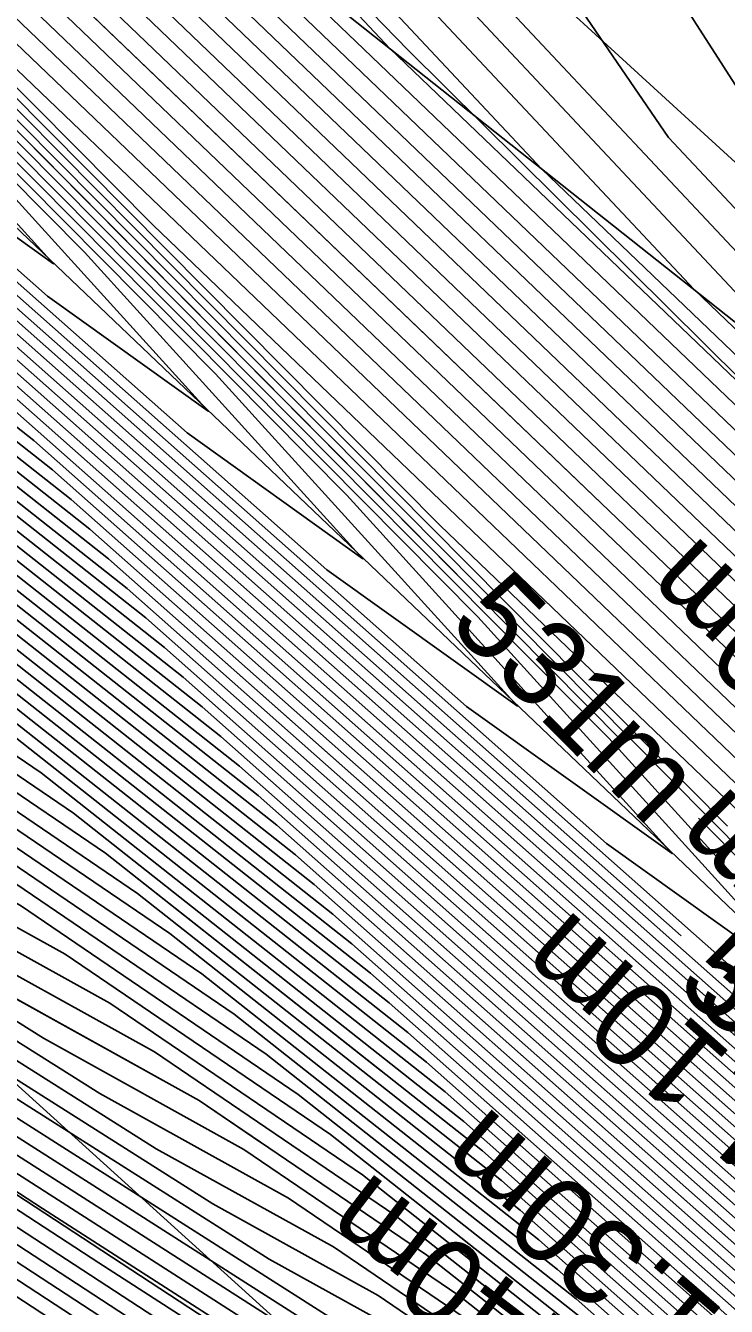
# Model space of a CAD drawing. Extents: x -866683 to -866410, y -1041951 to -1040252.
# Drawn here: x -866433.64 to -866431.189, y -1041924.913 to -1041920.429 of the extents above; entities that cross this region are included whole.
import ezdxf

# ---------------------------------------------------------------- set-up
doc = ezdxf.new("R2010")
doc.units = 0
for name, color, linetype in [('BREAKLINE', 7, 'Continuous'), ('V-HL', 7, 'Continuous'), ('V-POPIS', 7, 'Continuous'), ('V-VEDL', 7, 'Continuous'), ('V_po_cm', 7, 'Continuous')]:
    doc.layers.add(name, color=color, linetype=linetype)

msp = doc.modelspace()

# ---------------------------------------------------------------- linework, layer by layer
at = {"layer": 'BREAKLINE'}
for points in [[(-866451.679, -1041950.508), (-866455.618, -1041922.473), (-866456.719, -1041912.396), (-866455.207, -1041909.853), (-866453.752, -1041908.342), (-866450, -1041907.538), (-866447.7, -1041908.076), (-866445.165, -1041909.459), (-866437.422, -1041915.176), (-866426.565, -1041925.108), (-866438.22, -1041915.868), (-866445.312, -1041910.554), (-866447.7, -1041908.076)], [(-866445.626, -1041911.77), (-866438.844, -1041916.202), (-866428.169, -1041926.387)], [(-866430.202, -1041927.282), (-866445.247, -1041913.64), (-866449.543, -1041926.354), (-866449.641, -1041934.033), (-866450.183, -1041936.864), (-866452.267, -1041937.851), (-866451.576, -1041945.087)]]:
    msp.add_lwpolyline(points, dxfattribs=at)
at = {"layer": 'V-HL'}
for points in [[(-866432.13, -1041922.3514), (-866435.3498, -1041919.1014), (-866436.3778, -1041918.1143)], [(-866435.9248, -1041919.7422), (-866434.0049, -1041921.2589), (-866431.3462, -1041923.6159)], [(-866430.7569, -1041923.7374), (-866431.2855, -1041923.2039)]]:
    msp.add_lwpolyline(points, dxfattribs=at)
at = {"layer": 'V-VEDL'}
for points in [[(-866449.345, -1041907.5366), (-866448.9556, -1041907.8532), (-866448.4862, -1041908.0339), (-866448.3105, -1041908.3809), (-866448.4285, -1041908.8942), (-866448.8402, -1041909.5738), (-866449.0019, -1041910.1655), (-866448.9134, -1041910.6692), (-866448.5749, -1041911.085), (-866448.5335, -1041911.4362), (-866448.7893, -1041911.7228), (-866449.3421, -1041911.9448), (-866449.4057, -1041912.585), (-866448.98, -1041913.6435), (-866448.0652, -1041915.1203), (-866447.345, -1041916.0757), (-866446.8195, -1041916.5099), (-866446.4887, -1041916.4228), (-866444.7099, -1041917.3864), (-866441.483, -1041919.4008), (-866432.1333, -1041925.5308)], [(-866427.6159, -1041925.946), (-866434.3305, -1041919.5086), (-866436.6195, -1041917.3087), (-866437.8401, -1041916.1275), (-866437.9924, -1041915.9651), (-866438.251, -1041915.7527), (-866438.6158, -1041915.4903), (-866439.5581, -1041914.8654)], [(-866441.6705, -1041916.8829), (-866437.7247, -1041919.072), (-866435.6089, -1041920.5114), (-866433.3503, -1041922.2956), (-866428.5474, -1041926.5536)], [(-866427.1131, -1041925.545), (-866430.615, -1041922.1877), (-866432.3013, -1041920.5151), (-866433.9232, -1041918.8486)], [(-866439.2862, -1041919.0449), (-866436.1607, -1041920.7789), (-866434.4848, -1041921.919), (-866432.6958, -1041923.3322), (-866428.8914, -1041926.705)], [(-866436.9019, -1041921.2069), (-866434.5968, -1041922.4857), (-866433.3607, -1041923.3266), (-866432.0413, -1041924.3689), (-866429.2354, -1041926.8565)], [(-866429.5794, -1041927.0079), (-866431.3867, -1041925.4056), (-866432.2366, -1041924.7342), (-866433.0328, -1041924.1926), (-866434.5176, -1041923.3688)]]:
    msp.add_lwpolyline(points, dxfattribs=at)
at = {"layer": 'V_po_cm'}
msp.add_lwpolyline([(-866447.3599, -1041911.0448), (-866445.9513, -1041912.7749), (-866444.619, -1041913.8303), (-866442.6588, -1041915.0759), (-866440.0707, -1041916.5117), (-866437.6107, -1041918.1202), (-866435.2789, -1041919.9012), (-866433.0752, -1041921.8549), (-866432.4602, -1041922.2952), (-866433.4339, -1041921.2221), (-866435.9962, -1041918.6357), (-866438.0089, -1041916.6902), (-866439.4718, -1041915.3858), (-866440.3849, -1041914.7224), (-866441.4494, -1041913.9281), (-866442.665, -1041913.0029), (-866444.032, -1041911.9468), (-866445.0847, -1041911.1336), (-866445.8231, -1041910.5632), (-866446.2472, -1041910.2357), (-866446.6064, -1041910.1437), (-866446.9008, -1041910.2871)], close=True, dxfattribs=at)
for points in [[(-866440.8633, -1041912.6351), (-866440.2737, -1041911.0786), (-866439.4746, -1041910.927), (-866438.1712, -1041911.4021), (-866436.3636, -1041912.5037), (-866434.7937, -1041914.0377), (-866433.4616, -1041916.004), (-866432.3673, -1041918.4026), (-866431.4043, -1041920.2505), (-866430.5728, -1041921.5477), (-866429.1727, -1041923.0406)], [(-866429.7049, -1041922.6187), (-866431.3908, -1041920.8211), (-866432.2605, -1041919.5473), (-866433.1571, -1041917.8985), (-866434.0804, -1041915.8746), (-866435.2044, -1041914.2156), (-866436.529, -1041912.9213), (-866438.0541, -1041911.9917), (-866439.1539, -1041911.5909), (-866439.8281, -1041911.7188), (-866440.3256, -1041913.0321)], [(-866439.7879, -1041913.4291), (-866439.3825, -1041912.359), (-866438.8331, -1041912.2548), (-866437.9371, -1041912.5814), (-866436.6943, -1041913.3388), (-866435.6151, -1041914.3934), (-866434.6992, -1041915.7453), (-866433.9469, -1041917.3943), (-866433.1167, -1041918.844), (-866432.2087, -1041920.0945), (-866430.2371, -1041922.1968)], [(-866449.4813, -1041912.5658), (-866449.0479, -1041913.6436), (-866448.1164, -1041915.1472), (-866447.3831, -1041916.12), (-866446.8481, -1041916.5621), (-866446.5112, -1041916.4734), (-866444.7001, -1041917.4545), (-866441.4146, -1041919.5055), (-866436.6547, -1041922.6262), (-866433.3844, -1041924.7606), (-866431.6036, -1041925.9086), (-866431.3124, -1041926.0701), (-866431.0001, -1041926.2826), (-866430.6667, -1041926.546), (-866429.9578, -1041927.1745)], [(-866449.3301, -1041912.6042), (-866448.9122, -1041913.6435), (-866448.0139, -1041915.0933), (-866447.3068, -1041916.0314), (-866446.7909, -1041916.4577), (-866446.4661, -1041916.3722), (-866444.7196, -1041917.3183), (-866441.5514, -1041919.296), (-866436.9616, -1041922.3053), (-866433.7773, -1041924.3805), (-866431.9985, -1041925.5217), (-866431.6252, -1041925.7288), (-866431.2249, -1041926.0011), (-866430.7976, -1041926.3386), (-866429.889, -1041927.1442)], [(-866429.8546, -1041927.129), (-866430.8631, -1041926.2349), (-866431.3373, -1041925.8603), (-866431.7816, -1041925.5581), (-866432.1959, -1041925.3282), (-866433.9737, -1041924.1905), (-866437.115, -1041922.1448), (-866441.6199, -1041919.1913), (-866444.7294, -1041917.2502), (-866446.4435, -1041916.3216), (-866446.7623, -1041916.4055), (-866447.2687, -1041915.9871), (-866447.9627, -1041915.0664), (-866448.8443, -1041913.6434), (-866449.2545, -1041912.6234)], [(-866429.8202, -1041927.1139), (-866430.9285, -1041926.1313), (-866431.4498, -1041925.7195), (-866431.938, -1041925.3874), (-866432.3933, -1041925.1348), (-866434.1701, -1041924.0005), (-866437.2685, -1041921.9844), (-866441.6883, -1041919.0865), (-866444.7391, -1041917.1821), (-866446.4209, -1041916.271), (-866446.7337, -1041916.3534), (-866447.2305, -1041915.9429), (-866447.9114, -1041915.0395), (-866448.7764, -1041913.6433), (-866449.1788, -1041912.6426)], [(-866439.2502, -1041913.8262), (-866438.9369, -1041912.9993), (-866438.5124, -1041912.9187), (-866437.82, -1041913.1711), (-866436.8597, -1041913.7564), (-866436.0257, -1041914.5713), (-866435.318, -1041915.6159), (-866434.7367, -1041916.8901), (-866433.9729, -1041918.1408), (-866433.0266, -1041919.3679), (-866430.7693, -1041921.7748)], [(-866431.3015, -1041921.3529), (-866433.8446, -1041918.6413), (-866434.829, -1041917.4376), (-866435.5265, -1041916.386), (-866435.9369, -1041915.4865), (-866436.4364, -1041914.7491), (-866437.0251, -1041914.1739), (-866437.703, -1041913.7608), (-866438.1917, -1041913.5826), (-866438.4914, -1041913.6395), (-866438.7125, -1041914.2232)], [(-866449.3873, -1041913.6439), (-866448.3726, -1041915.2817), (-866447.5738, -1041916.3414), (-866446.991, -1041916.823), (-866446.6241, -1041916.7264), (-866444.6513, -1041917.7951), (-866441.0724, -1041920.0292), (-866435.8875, -1041923.4286), (-866432.4023, -1041925.7108), (-866430.6166, -1041926.8758), (-866430.5304, -1041926.9236), (-866430.4381, -1041926.9864), (-866430.3395, -1041927.0643), (-866430.1298, -1041927.2502)], [(-866430.0954, -1041927.2351), (-866430.4049, -1041926.9606), (-866430.5505, -1041926.8456), (-866430.6868, -1041926.7529), (-866430.814, -1041926.6823), (-866432.5987, -1041925.5207), (-866436.041, -1041923.2681), (-866441.1408, -1041919.9245), (-866444.661, -1041917.727), (-866446.6015, -1041916.6758), (-866446.9624, -1041916.7708), (-866447.5357, -1041916.2972), (-866448.3213, -1041915.2548), (-866449.3194, -1041913.6438)], [(-866449.2515, -1041913.6438), (-866448.2701, -1041915.2279), (-866447.4975, -1041916.2529), (-866446.9338, -1041916.7186), (-866446.579, -1041916.6252), (-866444.6708, -1041917.6589), (-866441.2093, -1041919.8197), (-866436.1944, -1041923.1077), (-866432.7951, -1041925.3307), (-866431.0114, -1041926.4889), (-866430.8432, -1041926.5822), (-866430.6629, -1041926.7049), (-866430.4704, -1041926.857), (-866430.061, -1041927.2199)], [(-866430.0266, -1041927.2048), (-866430.5358, -1041926.7533), (-866430.7753, -1041926.5641), (-866430.9996, -1041926.4115), (-866431.2088, -1041926.2954), (-866432.9916, -1041925.1407), (-866436.3479, -1041922.9472), (-866441.2777, -1041919.715), (-866444.6806, -1041917.5908), (-866446.5564, -1041916.5746), (-866446.9052, -1041916.6664), (-866447.4594, -1041916.2086), (-866448.2189, -1041915.201), (-866449.1837, -1041913.6437)], [(-866449.1158, -1041913.6437), (-866448.1676, -1041915.1741), (-866447.4212, -1041916.1643), (-866446.8766, -1041916.6143), (-866446.5338, -1041916.524), (-866444.6903, -1041917.5227), (-866441.3461, -1041919.6102), (-866436.5013, -1041922.7867), (-866433.188, -1041924.9506), (-866431.4062, -1041926.102), (-866431.156, -1041926.2408), (-866430.8877, -1041926.4234), (-866430.6013, -1041926.6496), (-866429.9922, -1041927.1896)], [(-866431.8337, -1041920.931), (-866434.6625, -1041917.9147), (-866435.6852, -1041916.7343), (-866436.3163, -1041915.8818), (-866436.5557, -1041915.3571), (-866436.8471, -1041914.927), (-866437.1905, -1041914.5914), (-866437.5859, -1041914.3504), (-866437.871, -1041914.2465), (-866438.0458, -1041914.2797), (-866438.1748, -1041914.6202)], [(-866427.6662, -1041925.9861), (-866438.22, -1041915.868)], [(-866437.1556, -1041916.7118), (-866427.5656, -1041925.9059)], [(-866427.7165, -1041926.0262), (-866437.2149, -1041916.9199)], [(-866427.5153, -1041925.8658), (-866436.6234, -1041917.1338)], [(-866427.4651, -1041925.8257), (-866436.0912, -1041917.5557)], [(-866436.6255, -1041917.6643), (-866433.1945, -1041921.1275)], [(-866432.3659, -1041920.5091), (-866434.8358, -1041917.8754)], [(-866427.7667, -1041926.0662), (-866436.2098, -1041917.9718)], [(-866427.4148, -1041925.7856), (-866435.559, -1041917.9776)], [(-866436.3065, -1041918.0236), (-866432.1894, -1041922.1794)], [(-866429.5106, -1041926.9776), (-866431.5176, -1041925.1983), (-866432.4615, -1041924.4527), (-866433.3456, -1041923.8512), (-866434.17, -1041923.3938), (-866435.9379, -1041922.2901), (-866438.6494, -1041920.5402), (-866442.3042, -1041918.1439)], [(-866429.545, -1041926.9928), (-866431.4522, -1041925.3019), (-866432.349, -1041924.5935), (-866433.1892, -1041924.0219), (-866433.9726, -1041923.5873), (-866435.7415, -1041922.4802), (-866438.4959, -1041920.7006), (-866442.2358, -1041918.2486)], [(-866435.9876, -1041918.3828), (-866431.1843, -1041923.2313)], [(-866427.3645, -1041925.7455), (-866435.0268, -1041918.3995)], [(-866429.6138, -1041927.023), (-866431.3213, -1041925.5093), (-866432.1242, -1041924.875), (-866432.8764, -1041924.3633), (-866433.5778, -1041923.9742), (-866435.3487, -1041922.8603), (-866438.1891, -1041921.0216), (-866442.0989, -1041918.4581)], [(-866435.581, -1041919.5877), (-866433.5641, -1041921.3758), (-866433.0012, -1041921.7788), (-866433.8924, -1041920.7967), (-866436.2376, -1041918.4294)], [(-866437.2281, -1041918.5416), (-866434.6746, -1041920.5282), (-866432.0974, -1041922.813), (-866431.3782, -1041923.3279), (-866432.5169, -1041922.073), (-866435.5136, -1041919.0482)], [(-866429.6482, -1041927.0382), (-866431.2558, -1041925.6129), (-866432.0118, -1041925.0157), (-866432.72, -1041924.534), (-866433.3804, -1041924.1676), (-866435.1522, -1041923.0503), (-866438.0356, -1041921.182), (-866442.0305, -1041918.5628)], [(-866441.9621, -1041918.6676), (-866437.8822, -1041921.3425), (-866434.9558, -1041923.2403), (-866433.183, -1041924.361), (-866432.5636, -1041924.7046), (-866431.8994, -1041925.1565), (-866431.1904, -1041925.7166), (-866429.6826, -1041927.0533)], [(-866429.717, -1041927.0685), (-866431.1249, -1041925.8203), (-866431.787, -1041925.2973), (-866432.4072, -1041924.8753), (-866432.9855, -1041924.5545), (-866434.7594, -1041923.4304), (-866437.7288, -1041921.503), (-866441.8936, -1041918.7723)], [(-866437.0368, -1041918.7523), (-866434.3725, -1041920.8417), (-866431.6085, -1041923.292), (-866430.8372, -1041923.8443), (-866432.0584, -1041922.4984), (-866435.2722, -1041919.2544)], [(-866435.6687, -1041918.7421), (-866430.1792, -1041924.2832)], [(-866434.9767, -1041920.2147), (-866432.5863, -1041922.3339), (-866431.9192, -1041922.8115), (-866432.9754, -1041921.6475), (-866435.7549, -1041918.8419)], [(-866427.3142, -1041925.7054), (-866434.4947, -1041918.8214)], [(-866429.7514, -1041927.0836), (-866431.0594, -1041925.9239), (-866431.6746, -1041925.438), (-866432.2508, -1041925.046), (-866432.7881, -1041924.7479), (-866434.563, -1041923.6204), (-866437.5753, -1041921.6634), (-866441.8252, -1041918.877)], [(-866429.7858, -1041927.0988), (-866430.994, -1041926.0276), (-866431.5622, -1041925.5788), (-866432.0944, -1041925.2167), (-866432.5907, -1041924.9414), (-866434.3665, -1041923.8104), (-866437.4219, -1041921.8239), (-866441.7568, -1041918.9818)], [(-866436.8455, -1041918.963), (-866434.0703, -1041921.1552), (-866431.1197, -1041923.7711), (-866430.2962, -1041924.3606), (-866431.6, -1041922.9238), (-866435.0309, -1041919.4606)], [(-866427.817, -1041926.1063), (-866435.2047, -1041919.0237)], [(-866429.201, -1041926.8413), (-866432.1067, -1041924.2653), (-866433.4731, -1041923.1858), (-866434.7532, -1041922.315), (-866435.9468, -1041921.6529), (-866437.7058, -1041920.5798), (-866440.0303, -1041919.0959)], [(-866434.656, -1041919.1965), (-866431.6242, -1041922.1031)], [(-866437.5683, -1041919.2427), (-866435.4965, -1041920.6521), (-866433.2849, -1041922.3992), (-866428.5818, -1041926.5687)], [(-866428.2378, -1041926.4173), (-866433.9394, -1041921.3625), (-866436.6206, -1041919.2445)], [(-866433.9625, -1041919.2433), (-866427.2639, -1041925.6653)], [(-866435.8831, -1041919.2742), (-866434.053, -1041920.8968), (-866433.5422, -1041921.2624), (-866434.3509, -1041920.3712)], [(-866428.2722, -1041926.4324), (-866433.874, -1041921.4662), (-866436.5082, -1041919.3853)], [(-866439.7234, -1041919.4169), (-866437.3129, -1041920.9599), (-866435.5519, -1041922.0397), (-866434.4404, -1041922.6564), (-866433.2483, -1041923.4674), (-866431.9758, -1041924.4726), (-866429.2698, -1041926.8716)], [(-866438.8843, -1041919.4396), (-866437.1312, -1041920.4922), (-866435.6915, -1041921.2909), (-866434.1476, -1041922.3413), (-866432.4994, -1041923.6432), (-866428.9946, -1041926.7505)], [(-866437.4119, -1041919.4134), (-866435.3841, -1041920.7929), (-866433.2194, -1041922.5029), (-866428.6162, -1041926.5839)], [(-866438.1183, -1041919.525), (-866436.4735, -1041920.4375), (-866434.7097, -1041921.6375), (-866432.8267, -1041923.1249), (-866428.8226, -1041926.6747)], [(-866428.3066, -1041926.4476), (-866433.8085, -1041921.5699), (-866436.3958, -1041919.526)], [(-866429.3042, -1041926.8867), (-866431.9103, -1041924.5763), (-866433.1359, -1041923.6081), (-866434.284, -1041922.8271), (-866435.3545, -1041922.2332), (-866437.1165, -1041921.1499), (-866439.57, -1041919.5773)], [(-866428.6506, -1041926.599), (-866433.154, -1041922.6066), (-866435.2717, -1041920.9337), (-866437.2555, -1041919.5841)], [(-866438.6879, -1041919.6296), (-866436.9338, -1041920.6857), (-866435.5351, -1041921.4616), (-866434.0352, -1041922.482), (-866432.434, -1041923.7469), (-866429.029, -1041926.7656)], [(-866428.341, -1041926.4627), (-866433.7431, -1041921.6735), (-866436.2834, -1041919.6668)], [(-866427.2136, -1041925.6252), (-866433.4303, -1041919.6653)], [(-866429.3386, -1041926.9019), (-866431.8449, -1041924.6799), (-866433.0235, -1041923.7489), (-866434.1276, -1041922.9978), (-866435.1571, -1041922.4266), (-866436.9201, -1041921.34), (-866439.4165, -1041919.7378)], [(-866437.9209, -1041919.7184), (-866436.3171, -1041920.6082), (-866434.5973, -1041921.7782), (-866432.7612, -1041923.2286), (-866428.857, -1041926.6899)], [(-866428.685, -1041926.6142), (-866433.0885, -1041922.7102), (-866435.1593, -1041921.0744), (-866437.0991, -1041919.7548)], [(-866438.4915, -1041919.8197), (-866436.7364, -1041920.8791), (-866435.3788, -1041921.6323), (-866433.9228, -1041922.6228), (-866432.3685, -1041923.8506), (-866429.0634, -1041926.7807)], [(-866428.3754, -1041926.4779), (-866433.6776, -1041921.7772), (-866436.171, -1041919.8076)], [(-866429.373, -1041926.917), (-866431.7794, -1041924.7836), (-866432.9111, -1041923.8896), (-866433.9712, -1041923.1685), (-866434.9597, -1041922.6201), (-866436.7237, -1041921.53), (-866439.2631, -1041919.8983)], [(-866428.7194, -1041926.6293), (-866433.0231, -1041922.8139), (-866435.0469, -1041921.2152), (-866436.9427, -1041919.9254)], [(-866428.4098, -1041926.493), (-866433.6121, -1041921.8809), (-866436.0586, -1041919.9483)], [(-866431.5518, -1041922.935), (-866434.5077, -1041919.9514)], [(-866438.2951, -1041920.0097), (-866436.539, -1041921.0725), (-866435.2224, -1041921.803), (-866433.8104, -1041922.7636), (-866432.3031, -1041923.9542), (-866429.0978, -1041926.7959)], [(-866429.4074, -1041926.9322), (-866431.714, -1041924.8873), (-866432.7987, -1041924.0304), (-866433.8148, -1041923.3392), (-866434.7623, -1041922.8135), (-866436.5272, -1041921.72), (-866439.1097, -1041920.0587)], [(-866437.5261, -1041920.1053), (-866436.0043, -1041920.9496), (-866434.3724, -1041922.0597), (-866432.6303, -1041923.4359), (-866428.9258, -1041926.7202)], [(-866436.7863, -1041920.0961), (-866434.9345, -1041921.3559), (-866432.9576, -1041922.9176), (-866428.7538, -1041926.6444)], [(-866428.4442, -1041926.5082), (-866433.5467, -1041921.9845), (-866435.9462, -1041920.0891)], [(-866427.8673, -1041926.1464), (-866434.1996, -1041920.0756)], [(-866427.1634, -1041925.5851), (-866432.8981, -1041920.0872)], [(-866429.1322, -1041926.811), (-866432.2376, -1041924.0579), (-866433.698, -1041922.9043), (-866435.066, -1041921.9737), (-866436.3416, -1041921.266), (-866438.0986, -1041920.1998)], [(-866438.9562, -1041920.2192), (-866436.3308, -1041921.9101), (-866434.5649, -1041923.0069), (-866433.6584, -1041923.5098), (-866432.6863, -1041924.1712), (-866431.6485, -1041924.9909), (-866429.4418, -1041926.9473)], [(-866428.4786, -1041926.5233), (-866433.4812, -1041922.0882), (-866435.8338, -1041920.2298)], [(-866428.9602, -1041926.7353), (-866432.5649, -1041923.5396), (-866434.26, -1041922.2005), (-866435.8479, -1041921.1202), (-866437.3287, -1041920.2988)], [(-866428.7882, -1041926.6596), (-866432.8922, -1041923.0212), (-866434.8221, -1041921.4967), (-866436.6299, -1041920.2668)], [(-866429.4762, -1041926.9625), (-866431.5831, -1041925.0946), (-866432.5739, -1041924.3119), (-866433.502, -1041923.6805), (-866434.3674, -1041923.2004), (-866436.1344, -1041922.1001), (-866438.8028, -1041920.3797)], [(-866428.513, -1041926.5384), (-866433.4158, -1041922.1919), (-866435.7214, -1041920.3706)], [(-866437.9022, -1041920.3898), (-866436.1442, -1041921.4594), (-866434.9096, -1041922.1444), (-866433.5856, -1041923.0451), (-866432.1722, -1041924.1616), (-866429.1666, -1041926.8262)], [(-866432.3659, -1041920.5091), (-866430.85, -1041921.9624)], [(-866432.0739, -1041923.4272), (-866433.3503, -1041922.2956), (-866435.3071, -1041920.7498)], [(-866434.5125, -1041920.8579), (-866434.0049, -1041921.2589), (-866431.3462, -1041923.6159)], [(-866431.8337, -1041920.931), (-866427.0628, -1041925.5049)], [(-866433.1945, -1041921.1275), (-866427.9176, -1041926.1865)], [(-866431.3015, -1041921.3529), (-866427.0125, -1041925.4648)], [(-866432.3948, -1041924.0896), (-866433.3607, -1041923.3266), (-866434.5968, -1041922.4857), (-866435.7493, -1041921.8463), (-866435.8822, -1041921.7651)], [(-866432.8177, -1041924.3389), (-866433.0328, -1041924.1926), (-866433.7752, -1041923.7807), (-866435.5451, -1041922.6702), (-866436.385, -1041922.1271)], [(-866427.9679, -1041926.2266), (-866432.1894, -1041922.1794)], [(-866430.4265, -1041925.3441), (-866432.6958, -1041923.3322), (-866433.5733, -1041922.6391)], [(-866432.88, -1041925.0213), (-866433.5808, -1041924.5706), (-866436.4008, -1041922.7314)]]:
    msp.add_lwpolyline(points, dxfattribs=at)

# ---------------------------------------------------------------- texts
at = {"layer": 'V-POPIS'}
for rotation, p in [(314.7322, (-866432.1669, -1041922.5273)), (318.4415, (-866431.3716, -1041923.7938))]:
    msp.add_text('531m', height=0.3, rotation=rotation, dxfattribs=at).set_placement(p)
at = {"layer": 'V_po_cm'}
for s, rotation, p in [('531.10m', 136.2076, (-866430.172, -1041923.2876)), ('531.00m', 134.7322, (-866430.0947, -1041924.1927)), ('531.10m', 138.4415, (-866430.5766, -1041924.5541)), ('531.00m', 318.4415, (-866431.3102, -1041923.8482)), ('531.30m', 139.1387, (-866430.8492, -1041925.2283)), ('531.40m', 142.5682, (-866431.2026, -1041925.3862))]:
    msp.add_text(s, height=0.3, rotation=rotation, dxfattribs=at).set_placement(p)

doc.saveas('drawing.dxf')
